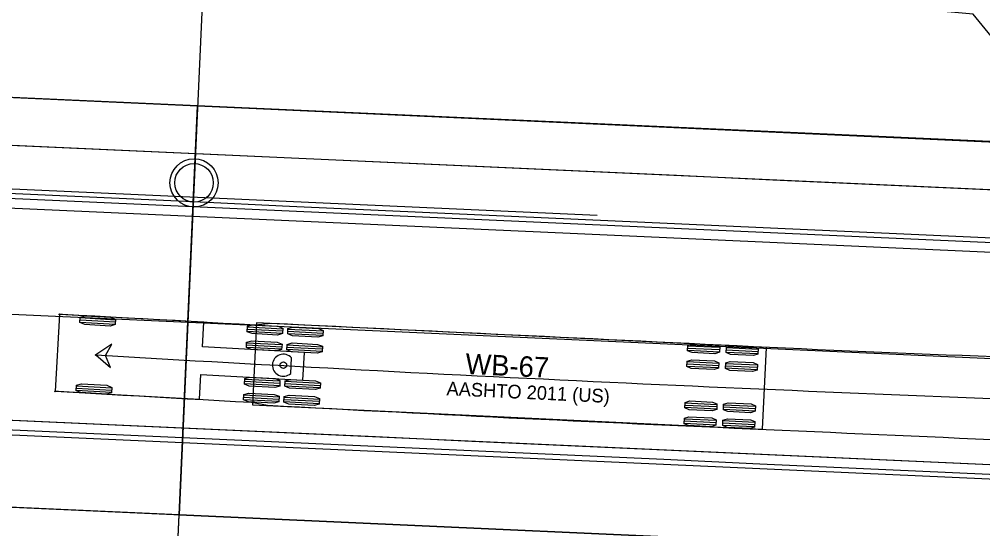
# Model space of a CAD drawing. Extents: x -70 to 701944, y -4 to 666871.
# Drawn here: x 667525.7 to 667625.7, y 656566.5 to 656619.3 of the extents above; entities that cross this region are included whole.
import ezdxf

# ---------------------------------------------------------------- set-up
doc = ezdxf.new("R2010")
doc.units = 0
for name, color, linetype in [('R_Detour', 7, 'Continuous'), ('R_Horz Alg', 7, 'Continuous'), ('R_No Plot', 7, 'Continuous'), ('R_Proposed Const Limits', 7, 'Continuous'), ('R_Proposed Road', 7, 'Continuous'), ('R_Striping', 7, 'Continuous'), ('R_Water', 7, 'Continuous'), ('T_Indications', 7, 'Continuous'), ('T_Vehicle Path Lt Minor', 7, 'Continuous')]:
    doc.layers.add(name, color=color, linetype=linetype)

msp = doc.modelspace()

# ---------------------------------------------------------------- linework, layer by layer
at = {"layer": 'R_Detour'}
for p in [(667548.48, 656705.5), (667536.22, 656434.12)]:
    msp.add_line(p, (667542.27, 656567.89), dxfattribs=at)
at = {"layer": 'R_Horz Alg'}
msp.add_line((667725.26, 656559.62), (664961.47, 656684.5), dxfattribs=at)
at = {"layer": 'R_No Plot'}
for p, q in [((667813.84, 656555.62), (664810.54, 656691.32)), ((667725.26, 656559.62), (664961.47, 656684.5))]:
    msp.add_line(p, q, dxfattribs=at)
for points in [[(667379.41, 656619), (667421.96, 656615.87), (667544.18, 656610.35), (667542.27, 656567.89), (667411.81, 656573.78), (667377.31, 656571.83)], [(667544.18, 656610.35), (667694.03, 656603.54), (667692.11, 656561.12), (667542.27, 656567.89)], [(667377.28, 656571.83), (667374.86, 656518.34), (667415.23, 656519.07), (667539.81, 656513.45), (667542.27, 656567.89), (667411.81, 656573.78)], [(667542.27, 656567.89), (667692.11, 656561.12), (667689.65, 656506.68), (667539.81, 656513.45)]]:
    msp.add_lwpolyline(points, close=True, dxfattribs=at)
msp.add_circle((667543.82, 656602.35), 2.5, dxfattribs=at)
at = {"layer": 'R_Proposed Const Limits'}
msp.add_lwpolyline([(667674.08, 656605.17), (667664.51, 656614.74), (667654.44, 656613.45), (667644.32, 656611.17), (667634.18, 656608.25), (667624.7, 656619.84), (667614.73, 656620.73), (667604.76, 656621.62), (667594.78, 656622.5), (667584.81, 656623.38), (667574.84, 656624.16), (667564.84, 656624.36), (667554.84, 656624.55), (667544.83, 656624.69), (667534.83, 656624.88), (667524.83, 656625.02), (667514.82, 656624.98), (667514.21, 656624.8), (667504.67, 656621.99), (667494.53, 656619.19), (667484.25, 656613.22), (667474.3, 656614.49), (667464.29, 656614.4), (667454.29, 656614.75)], dxfattribs=at)
at = {"layer": 'R_Proposed Road'}
for p, q in [((667585.68, 656598.96), (667419.18, 656606.49)), ((667725.67, 656568.61), (667418.1, 656582.51))]:
    msp.add_line(p, q, dxfattribs=at)
for points in [[(667724, 656602.22), (667714.01, 656602.67), (667704.02, 656603.13), (667694.03, 656603.58), (667684.04, 656604.03), (667674.05, 656604.48), (667664.06, 656604.93), (667654.07, 656605.38), (667644.08, 656605.83), (667634.09, 656606.28), (667624.1, 656606.74), (667614.11, 656607.19), (667604.12, 656607.64), (667594.13, 656608.09), (667584.14, 656608.54), (667574.15, 656608.99), (667564.16, 656609.44), (667554.17, 656609.9), (667544.18, 656610.35), (667534.19, 656610.8), (667524.21, 656611.25)], [(667723.78, 656597.23), (667713.79, 656597.68), (667703.8, 656598.13), (667693.81, 656598.58), (667683.82, 656599.03), (667673.83, 656599.48), (667663.84, 656599.94), (667653.85, 656600.39), (667643.86, 656600.84), (667633.87, 656601.29), (667623.88, 656601.74), (667613.89, 656602.19), (667603.9, 656602.64), (667593.91, 656603.1), (667583.92, 656603.55), (667573.93, 656604), (667563.94, 656604.45), (667553.95, 656604.9), (667543.96, 656605.35), (667533.97, 656605.8), (667523.98, 656606.25)], [(667723.55, 656592.23), (667713.56, 656592.68), (667703.57, 656593.14), (667693.58, 656593.59), (667683.59, 656594.04), (667673.6, 656594.49), (667663.61, 656594.94), (667653.62, 656595.39), (667643.63, 656595.84), (667633.64, 656596.29), (667623.65, 656596.75), (667613.66, 656597.2), (667603.67, 656597.65), (667593.68, 656598.1), (667583.69, 656598.55), (667573.7, 656599), (667563.71, 656599.45), (667553.72, 656599.91), (667543.73, 656600.36), (667533.74, 656600.81), (667523.75, 656601.26)], [(667723.53, 656591.73), (667713.54, 656592.18), (667703.55, 656592.64), (667693.56, 656593.09), (667683.57, 656593.54), (667673.58, 656593.99), (667663.59, 656594.44), (667653.6, 656594.89), (667643.61, 656595.34), (667633.62, 656595.8), (667623.63, 656596.25), (667613.64, 656596.7), (667603.65, 656597.15), (667593.66, 656597.6), (667583.67, 656598.05), (667573.68, 656598.5), (667563.69, 656598.95), (667553.7, 656599.41), (667543.71, 656599.86), (667533.72, 656600.31), (667523.73, 656600.76)], [(667723.48, 656590.73), (667713.49, 656591.19), (667703.5, 656591.64), (667693.51, 656592.09), (667683.52, 656592.54), (667673.53, 656592.99), (667663.54, 656593.44), (667653.55, 656593.89), (667643.56, 656594.34), (667633.57, 656594.8), (667623.58, 656595.25), (667613.59, 656595.7), (667603.6, 656596.15), (667593.61, 656596.6), (667583.62, 656597.05), (667573.64, 656597.5), (667563.65, 656597.96), (667553.66, 656598.41), (667543.67, 656598.86), (667533.68, 656599.31), (667523.69, 656599.76)], [(667722.49, 656568.76), (667712.5, 656569.21), (667702.51, 656569.66), (667692.52, 656570.11), (667682.53, 656570.56), (667672.54, 656571.01), (667662.55, 656571.46), (667652.56, 656571.92), (667642.57, 656572.37), (667632.58, 656572.82), (667622.59, 656573.27), (667612.6, 656573.72), (667602.61, 656574.17), (667592.62, 656574.62), (667582.63, 656575.08), (667572.64, 656575.53), (667562.65, 656575.98), (667552.66, 656576.43), (667542.67, 656576.88), (667532.68, 656577.33), (667522.69, 656577.78)], [(667722.44, 656567.76), (667712.45, 656568.21), (667702.46, 656568.66), (667692.47, 656569.11), (667682.48, 656569.56), (667672.5, 656570.01), (667662.51, 656570.47), (667652.52, 656570.92), (667642.53, 656571.37), (667632.54, 656571.82), (667622.55, 656572.27), (667612.56, 656572.72), (667602.57, 656573.17), (667592.58, 656573.63), (667582.59, 656574.08), (667572.6, 656574.53), (667562.61, 656574.98), (667552.62, 656575.43), (667542.63, 656575.88), (667532.64, 656576.33), (667522.65, 656576.78)], [(667722.44, 656567.76), (667712.45, 656568.21), (667702.46, 656568.66), (667692.47, 656569.11), (667682.48, 656569.56), (667672.5, 656570.01), (667662.51, 656570.47), (667652.52, 656570.92), (667642.53, 656571.37), (667632.54, 656571.82), (667622.55, 656572.27), (667612.56, 656572.72), (667602.57, 656573.17), (667592.58, 656573.63), (667582.59, 656574.08), (667572.6, 656574.53), (667562.61, 656574.98), (667552.62, 656575.43), (667542.63, 656575.88), (667532.64, 656576.33), (667522.65, 656576.78)], [(667722.42, 656567.26), (667712.43, 656567.71), (667702.44, 656568.16), (667692.45, 656568.61), (667682.46, 656569.06), (667672.47, 656569.51), (667662.48, 656569.97), (667652.49, 656570.42), (667642.5, 656570.87), (667632.51, 656571.32), (667622.52, 656571.77), (667612.53, 656572.22), (667602.54, 656572.67), (667592.55, 656573.13), (667582.56, 656573.58), (667572.57, 656574.03), (667562.58, 656574.48), (667552.59, 656574.93), (667542.61, 656575.38), (667532.62, 656575.83), (667522.63, 656576.29)], [(667722.42, 656567.26), (667712.43, 656567.71), (667702.44, 656568.16), (667692.45, 656568.61), (667682.46, 656569.06), (667672.47, 656569.51), (667662.48, 656569.97), (667652.49, 656570.42), (667642.5, 656570.87), (667632.51, 656571.32), (667622.52, 656571.77), (667612.53, 656572.22), (667602.54, 656572.67), (667592.55, 656573.13), (667582.56, 656573.58), (667572.57, 656574.03), (667562.58, 656574.48), (667552.59, 656574.93), (667542.61, 656575.38), (667532.62, 656575.83), (667522.63, 656576.29)]]:
    msp.add_lwpolyline(points, dxfattribs=at)
at = {"layer": 'R_Striping'}
msp.add_lwpolyline([(667726.16, 656579.6), (667726.15, 656579.6), (667418.43, 656593.51), (667318.67, 656601.02), (667119.04, 656610.04)], dxfattribs=at)
at = {"layer": 'R_Water'}
msp.add_circle((667543.82, 656602.35), 2, dxfattribs=at)
at = {"layer": 'T_Indications'}
for p, q in [((667727.18, 656602.08), (667419.75, 656615.97)), ((667726.96, 656597.08), (667419.38, 656610.98))]:
    msp.add_line(p, q, dxfattribs=at)
at = {"layer": 'T_Vehicle Path Lt Minor'}
for p, q in [((667529.85, 656588.7), (667529.41, 656580.72)), ((667544.82, 656587.89), (667529.85, 656588.7)), ((667531.97, 656587.91), (667535.63, 656587.69)), ((667531.99, 656588.14), (667535.65, 656587.92)), ((667532, 656588.37), (667535.66, 656588.15)), ((667544.68, 656585.33), (667544.82, 656587.89)), ((667550.3, 656587.82), (667549.89, 656579.33)), ((667603.24, 656585.28), (667550.3, 656587.82)), ((667549.35, 656586.95), (667553.01, 656586.75)), ((667549.36, 656587.18), (667553.02, 656586.98)), ((667549.37, 656587.41), (667553.03, 656587.21)), ((667553.55, 656586.95), (667557.21, 656586.75)), ((667553.57, 656587.18), (667557.23, 656586.98)), ((667553.54, 656586.73), (667557.2, 656586.53)), ((667555.27, 656584.75), (667544.68, 656585.33)), ((667549.26, 656585.31), (667552.92, 656585.11)), ((667549.27, 656585.53), (667552.93, 656585.34)), ((667549.28, 656585.76), (667552.94, 656585.56)), ((667553.45, 656585.08), (667557.11, 656584.88)), ((667553.46, 656585.31), (667557.12, 656585.11)), ((667553.48, 656585.54), (667557.14, 656585.34)), ((667595.07, 656584.99), (667598.36, 656584.83)), ((667595.08, 656585.21), (667598.37, 656585.06)), ((667595.09, 656585.44), (667598.38, 656585.29)), ((667599.06, 656584.79), (667602.36, 656584.64)), ((667599.07, 656585.02), (667602.37, 656584.86)), ((667599.08, 656585.25), (667602.38, 656585.09)), ((667602.83, 656576.79), (667603.24, 656585.28)), ((667553.86, 656582.58), (667553.94, 656584.2)), ((667555.11, 656581.89), (667555.27, 656584.75)), ((667595.01, 656583.8), (667598.31, 656583.64)), ((667594.99, 656583.34), (667598.28, 656583.18)), ((667595, 656583.57), (667598.29, 656583.41)), ((667598.98, 656583.15), (667602.28, 656582.99)), ((667598.99, 656583.37), (667602.29, 656583.22)), ((667599, 656583.6), (667602.3, 656583.45)), ((667544.39, 656579.9), (667544.53, 656582.46)), ((667544.53, 656582.46), (667555.11, 656581.89)), ((667549.08, 656581.99), (667552.74, 656581.79)), ((667531.58, 656580.84), (667535.24, 656580.62)), ((667531.6, 656581.06), (667535.26, 656580.85)), ((667531.61, 656581.29), (667535.27, 656581.08)), ((667549.05, 656581.53), (667552.71, 656581.33)), ((667549.06, 656581.76), (667552.72, 656581.56)), ((667553.24, 656581.3), (667556.91, 656581.1)), ((667553.26, 656581.53), (667556.92, 656581.33)), ((667553.27, 656581.76), (667556.93, 656581.56)), ((667529.41, 656580.72), (667544.39, 656579.9)), ((667529.41, 656580.72), (667529.41, 656580.72)), ((667548.96, 656579.88), (667552.62, 656579.68)), ((667548.97, 656580.11), (667552.63, 656579.91)), ((667548.99, 656580.34), (667552.65, 656580.14)), ((667553.17, 656579.88), (667556.83, 656579.68)), ((667553.18, 656580.11), (667556.84, 656579.91)), ((667549.89, 656579.33), (667602.83, 656576.79)), ((667549.89, 656579.33), (667549.89, 656579.33)), ((667553.15, 656579.65), (667556.82, 656579.45)), ((667594.78, 656579.06), (667598.08, 656578.9)), ((667594.79, 656579.29), (667598.09, 656579.13)), ((667594.8, 656579.52), (667598.1, 656579.36)), ((667598.78, 656578.87), (667602.07, 656578.71)), ((667598.79, 656579.1), (667602.08, 656578.94)), ((667598.8, 656579.33), (667602.1, 656579.17)), ((667594.73, 656577.87), (667598.02, 656577.71)), ((667594.7, 656577.41), (667598, 656577.25)), ((667594.71, 656577.64), (667598.01, 656577.48)), ((667598.7, 656577.22), (667601.99, 656577.06)), ((667598.71, 656577.45), (667602.01, 656577.29)), ((667598.72, 656577.68), (667602.02, 656577.52))]:
    msp.add_line(p, q, dxfattribs=at)
for points in [[(667626.9, 656584.3), (667625.23, 656584.36), (667623.56, 656584.42), (667621.9, 656584.48), (667620.23, 656584.55), (667618.56, 656584.61), (667616.89, 656584.68), (667615.22, 656584.74), (667613.56, 656584.81), (667611.89, 656584.88), (667610.22, 656584.96), (667608.55, 656585.03), (667606.88, 656585.11), (667605.22, 656585.19), (667603.55, 656585.27), (667601.88, 656585.35), (667600.21, 656585.43), (667598.55, 656585.51), (667596.88, 656585.59), (667595.21, 656585.67), (667593.54, 656585.75), (667591.88, 656585.83), (667590.21, 656585.91), (667588.54, 656585.99), (667586.88, 656586.07), (667585.21, 656586.15), (667583.54, 656586.23), (667581.87, 656586.31), (667580.21, 656586.39), (667578.54, 656586.47), (667576.87, 656586.55), (667575.2, 656586.63), (667573.54, 656586.71), (667571.87, 656586.79), (667570.2, 656586.87), (667568.53, 656586.95), (667566.87, 656587.03), (667565.2, 656587.11), (667563.53, 656587.19), (667561.86, 656587.27), (667560.2, 656587.35), (667558.53, 656587.43), (667556.86, 656587.51), (667555.2, 656587.59), (667553.53, 656587.67), (667551.86, 656587.75), (667550.18, 656587.59), (667548.51, 656587.68), (667546.85, 656587.77), (667545.18, 656587.87), (667543.51, 656587.96), (667541.85, 656588.05), (667540.18, 656588.14), (667538.51, 656588.23), (667536.85, 656588.32), (667535.18, 656588.41), (667533.51, 656588.5), (667531.85, 656588.6), (667530.18, 656588.69), (667529.85, 656588.7)], [(667626.61, 656575.69), (667624.94, 656575.77), (667623.27, 656575.84), (667621.6, 656575.92), (667619.93, 656575.99), (667618.26, 656576.06), (667616.59, 656576.14), (667614.92, 656576.21), (667613.25, 656576.28), (667611.58, 656576.36), (667609.9, 656576.43), (667608.23, 656576.5), (667606.56, 656576.58), (667604.89, 656576.65), (667603.22, 656576.73), (667601.55, 656576.8), (667599.88, 656576.87), (667598.21, 656576.95), (667596.54, 656577.02), (667594.87, 656577.09), (667593.2, 656577.17), (667591.53, 656577.24), (667589.86, 656577.32), (667588.19, 656577.4), (667586.52, 656577.47), (667584.84, 656577.55), (667583.17, 656577.63), (667581.5, 656577.71), (667579.83, 656577.79), (667578.16, 656577.87), (667576.49, 656577.95), (667574.82, 656578.03), (667573.15, 656578.12), (667571.48, 656578.2), (667569.81, 656578.28), (667568.14, 656578.37), (667566.47, 656578.45), (667564.8, 656578.54), (667563.13, 656578.62), (667561.46, 656578.71), (667559.79, 656578.8), (667558.12, 656578.89), (667556.45, 656578.98), (667554.78, 656579.07), (667553.11, 656579.16), (667551.44, 656579.25), (667549.78, 656579.55), (667548.11, 656579.64), (667546.44, 656579.73), (667544.77, 656579.82), (667543.1, 656579.92), (667541.43, 656580.01), (667539.76, 656580.11), (667538.09, 656580.21), (667536.42, 656580.3), (667534.75, 656580.4), (667533.08, 656580.5), (667531.41, 656580.6), (667529.74, 656580.7), (667529.41, 656580.72)]]:
    msp.add_lwpolyline(points, dxfattribs=at)
for points in [[(667531.97, 656587.85), (667532, 656588.42), (667532.53, 656588.56), (667535.16, 656588.41), (667535.66, 656588.21), (667535.63, 656587.64), (667535.11, 656587.49), (667532.47, 656587.65)], [(667549.34, 656586.9), (667549.37, 656587.47), (667549.9, 656587.61), (667552.53, 656587.47), (667553.04, 656587.27), (667553, 656586.7), (667552.48, 656586.55), (667549.85, 656586.7)], [(667553.54, 656586.67), (667553.57, 656587.24), (667554.09, 656587.38), (667556.73, 656587.24), (667557.23, 656587.04), (667557.2, 656586.47), (667556.68, 656586.32), (667554.04, 656586.47)], [(667549.25, 656585.25), (667549.28, 656585.82), (667549.81, 656585.96), (667552.44, 656585.82), (667552.95, 656585.62), (667552.91, 656585.05), (667552.39, 656584.91), (667549.76, 656585.05)], [(667533.62, 656584.49), (667535.14, 656583.18), (667534.62, 656584.43), (667535.28, 656585.61)], [(667553.45, 656585.02), (667553.48, 656585.59), (667554, 656585.74), (667556.64, 656585.59), (667557.14, 656585.39), (667557.11, 656584.82), (667556.59, 656584.68), (667553.95, 656584.82)], [(667595.06, 656584.93), (667595.09, 656585.5), (667595.56, 656585.65), (667597.93, 656585.54), (667598.39, 656585.34), (667598.36, 656584.77), (667597.89, 656584.62), (667595.52, 656584.73)], [(667599.06, 656584.74), (667599.09, 656585.31), (667599.56, 656585.46), (667601.93, 656585.34), (667602.38, 656585.15), (667602.36, 656584.58), (667601.89, 656584.43), (667599.51, 656584.54)], [(667594.98, 656583.28), (667595.01, 656583.85), (667595.48, 656584), (667597.85, 656583.89), (667598.31, 656583.69), (667598.28, 656583.12), (667597.81, 656582.97), (667595.44, 656583.09)], [(667598.98, 656583.09), (667599.01, 656583.66), (667599.48, 656583.81), (667601.85, 656583.7), (667602.3, 656583.5), (667602.28, 656582.93), (667601.81, 656582.78), (667599.43, 656582.89)], [(667549.05, 656581.47), (667549.08, 656582.04), (667549.6, 656582.19), (667552.24, 656582.04), (667552.74, 656581.84), (667552.71, 656581.27), (667552.19, 656581.13), (667549.55, 656581.27)], [(667553.24, 656581.24), (667553.27, 656581.81), (667553.79, 656581.96), (667556.43, 656581.81), (667556.93, 656581.61), (667556.9, 656581.04), (667556.38, 656580.9), (667553.74, 656581.04)], [(667531.58, 656580.78), (667531.61, 656581.35), (667532.14, 656581.49), (667534.77, 656581.34), (667535.27, 656581.13), (667535.24, 656580.56), (667534.72, 656580.42), (667532.08, 656580.58)], [(667548.96, 656579.82), (667548.99, 656580.4), (667549.51, 656580.54), (667552.15, 656580.4), (667552.65, 656580.2), (667552.62, 656579.62), (667552.1, 656579.48), (667549.46, 656579.62)], [(667553.15, 656579.6), (667553.18, 656580.17), (667553.7, 656580.31), (667556.34, 656580.17), (667556.84, 656579.97), (667556.81, 656579.4), (667556.29, 656579.25), (667553.66, 656579.4)], [(667594.78, 656579), (667594.81, 656579.57), (667595.28, 656579.72), (667597.65, 656579.61), (667598.1, 656579.42), (667598.08, 656578.84), (667597.61, 656578.69), (667595.23, 656578.81)], [(667598.77, 656578.81), (667598.8, 656579.38), (667599.27, 656579.53), (667601.65, 656579.42), (667602.1, 656579.22), (667602.07, 656578.65), (667601.6, 656578.5), (667599.23, 656578.62)], [(667594.7, 656577.35), (667594.73, 656577.93), (667595.2, 656578.08), (667597.57, 656577.96), (667598.02, 656577.77), (667598, 656577.2), (667597.53, 656577.05), (667595.15, 656577.16)], [(667598.7, 656577.16), (667598.72, 656577.73), (667599.19, 656577.88), (667601.57, 656577.77), (667602.02, 656577.58), (667601.99, 656577), (667601.52, 656576.85), (667599.15, 656576.97)]]:
    msp.add_lwpolyline(points, close=True, dxfattribs=at)
for centre, radius in [((667529.85, 656588.7), 0.0417), ((667533.62, 656584.49), 0.0417), ((667553.09, 656583.43), 0.34), ((667529.41, 656580.72), 0.0417)]:
    msp.add_circle(centre, radius, dxfattribs=at)
for centre, radius, start, end in [((667797.21, 661061.35), 4484.61, 266.63049, 268.03939), ((667553.09, 656583.43), 1.14, 41.8817, 311.8817)]:
    msp.add_arc(centre, radius, start, end, dxfattribs=at)

# ---------------------------------------------------------------- texts
for s, height, p in [('WB-67', 2.125, (667571.95, 656582.53)), ('AASHTO 2011 (US)', 1.4167, (667570.01, 656580.32))]:
    msp.add_text(s, height=height, rotation=357.2538, dxfattribs=at).set_placement(p)

doc.saveas('drawing.dxf')
